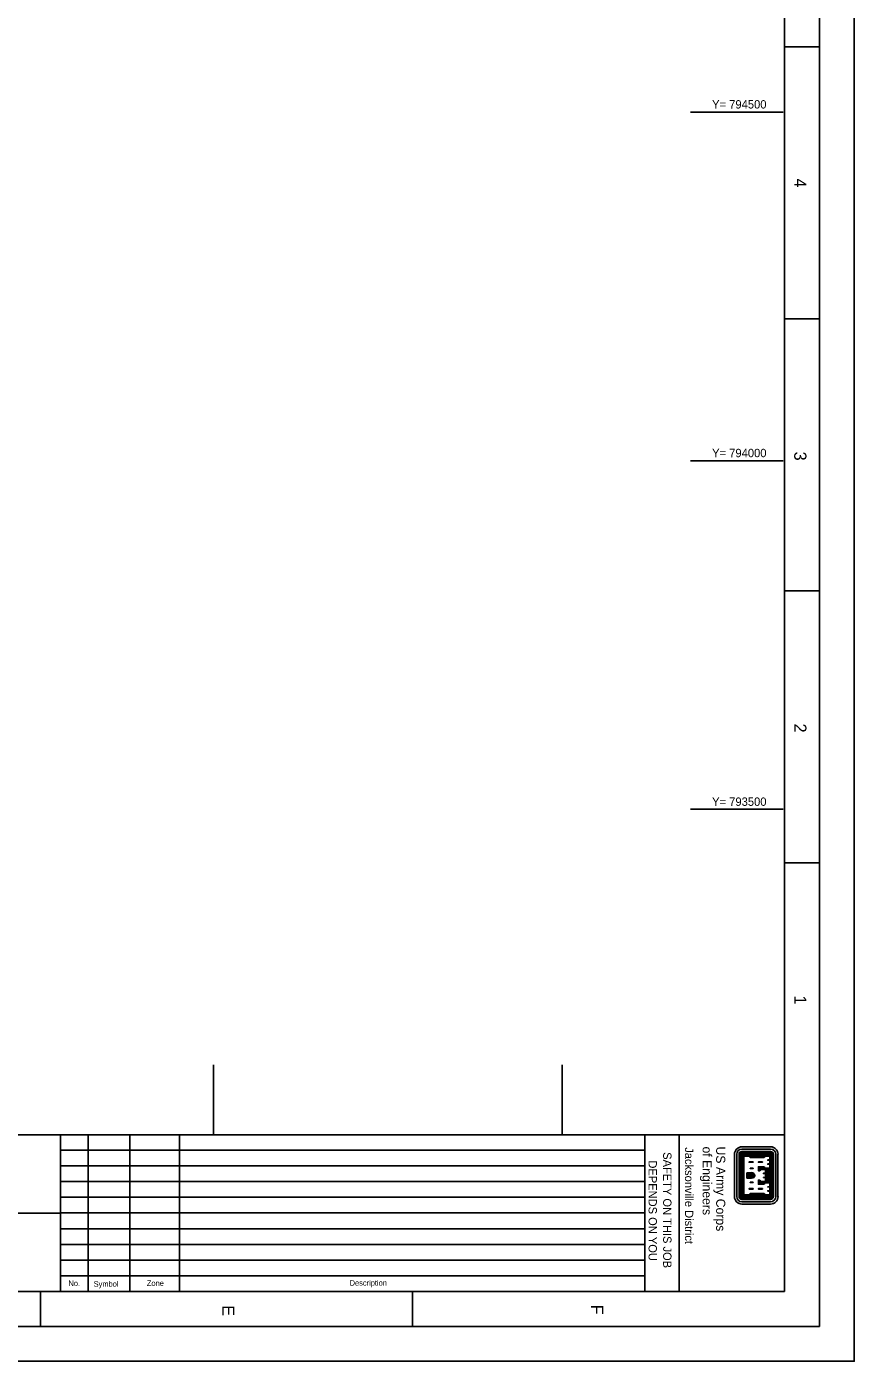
# Model space of a CAD drawing. Extents: x 604519 to 607919, y 792708 to 797108.
# Drawn here: x 606732 to 607919, y 792708 to 794622 of the extents above; entities that cross this region are included whole.
import ezdxf

# ---------------------------------------------------------------- set-up
doc = ezdxf.new("R2010")
doc.units = 0
for name, color, linetype in [('G-ANNO-NPLT', 7, 'Continuous'), ('G-ANNO-TEXT-LOGO', 7, 'Continuous'), ('G-ANNO-TEXT-TTLB', 7, 'Continuous'), ('G-ANNO-TTLB', 7, 'Continuous'), ('V-TOPO-COOR-STAT', 7, 'Continuous')]:
    doc.layers.add(name, color=color, linetype=linetype)

msp = doc.modelspace()

# ---------------------------------------------------------------- linework, layer by layer
at = {"layer": 'G-ANNO-NPLT'}
msp.add_lwpolyline([(607918.9, 797108.4), (607918.9, 792708.4), (604519, 792708.4), (604519, 797108.4)], close=True, dxfattribs=at)
msp.add_lwpolyline([(607868.9, 792708.4), (607918.9, 792708.4), (607918.9, 792758.4)], dxfattribs=at)
at = {"layer": 'G-ANNO-TEXT-LOGO'}
for p, q in [((607798.8, 793016), (607757.8, 793016)), ((607757.8, 793012.8), (607798.8, 793012.8)), ((607747, 793005.3), (607747, 792944.5)), ((607750.3, 792944.5), (607750.3, 793005.3)), ((607753.8, 792944.5), (607753.8, 793005.3)), ((607754.6, 792944.5), (607754.6, 793005.3)), ((607755.5, 792944.5), (607755.5, 793005.3)), ((607756.4, 792944.5), (607756.4, 793005.3)), ((607757.2, 792944.5), (607757.2, 793005.3)), ((607798.8, 793009.3), (607757.8, 793009.3)), ((607798.8, 793008.4), (607757.8, 793008.4)), ((607798.8, 793007.6), (607757.8, 793007.6)), ((607798.8, 793006.7), (607757.8, 793006.7)), ((607798.8, 793005.8), (607757.8, 793005.8)), ((607758.1, 792944.9), (607758.1, 793004.9)), ((607798.8, 793004.9), (607758.1, 793004.9)), ((607759, 792945.7), (607759, 793004.1)), ((607798.8, 793004.1), (607759, 793004.1)), ((607790.1, 793003.4), (607769.1, 793003.4)), ((607789.2, 793002.5), (607770.1, 793002.5)), ((607799.4, 792944.5), (607799.4, 793005.3)), ((607800.3, 792944.5), (607800.3, 793005.3)), ((607801.1, 792944.5), (607801.1, 793005.3)), ((607802, 792944.5), (607802, 793005.3)), ((607802.9, 792944.5), (607802.9, 793005.3)), ((607806.3, 793005.3), (607806.3, 792944.5)), ((607809.5, 792944.5), (607809.5, 793005.3)), ((607764.9, 792978.9), (607771.6, 792978.9)), ((607764.9, 792978.9), (607764.9, 792970.9)), ((607764.9, 792978.1), (607771.6, 792978.1)), ((607764.9, 792977.2), (607771.6, 792977.2)), ((607764.9, 792976.3), (607771.6, 792976.3)), ((607764.9, 792975.5), (607771.6, 792975.5)), ((607764.9, 792974.3), (607771.6, 792974.3)), ((607764.9, 792973.5), (607771.6, 792973.5)), ((607764.9, 792972.6), (607771.6, 792972.6)), ((607793.4, 792984.2), (607793.4, 792965.6)), ((607794.3, 792984.2), (607794.3, 792965.6)), ((607795.1, 792984.2), (607795.1, 792965.6)), ((607796, 792984.2), (607796, 792965.6)), ((607796.9, 792984.2), (607796.9, 792965.6)), ((607797.7, 792984.2), (607797.7, 792965.6)), ((607798.6, 792984.2), (607798.6, 792965.6)), ((607764.9, 792971.7), (607771.6, 792971.7)), ((607764.9, 792970.9), (607771.6, 792970.9)), ((607798.8, 792944), (607757.8, 792944)), ((607798.8, 792943.1), (607757.8, 792943.1)), ((607798.8, 792942.3), (607757.8, 792942.3)), ((607798.8, 792941.4), (607757.8, 792941.4)), ((607798.8, 792940.5), (607757.8, 792940.5)), ((607798.8, 792937.1), (607757.8, 792937.1)), ((607757.8, 792933.8), (607798.8, 792933.8)), ((607798.8, 792944.9), (607758.1, 792944.9)), ((607798.8, 792945.7), (607759, 792945.7)), ((607790, 792946.4), (607769.2, 792946.4)), ((607789.2, 792947.3), (607770.1, 792947.3))]:
    msp.add_line(p, q, dxfattribs=at)
for points in [[(607798.8, 793003.4), (607790.9, 793003.4), (607789.2, 793001.7), (607770.1, 793001.7), (607768.3, 793003.4), (607759.6, 793003.4), (607759.6, 792946.4), (607768.3, 792946.4), (607770.1, 792948.2), (607789.2, 792948.2), (607790.9, 792946.4), (607798.8, 792946.4), (607798.8, 792953.9), (607798.8, 792959.7), (607798.8, 792965.1), (607790.9, 792965.1), (607789.2, 792963.2), (607782.2, 792963.2), (607782.2, 792967.4), (607782.9, 792967.4), (607784.7, 792965.6), (607792.5, 792965.6), (607792.5, 792973.1), (607792.5, 792978.9), (607792.5, 792984.2), (607784.7, 792984.2), (607782.9, 792982.4), (607782.2, 792982.4), (607782.2, 792986.6), (607789.2, 792986.6), (607790.9, 792984.8), (607798.8, 792984.8), (607798.8, 792992.3), (607798.8, 792998.1), (607798.8, 793003.4)], [(607797.9, 793002.6), (607791.3, 793002.6), (607789.5, 793000.8), (607769.7, 793000.8), (607767.9, 793002.6), (607760.5, 793002.6), (607760.5, 792947.2), (607767.9, 792947.2), (607769.7, 792949.1), (607789.5, 792949.1), (607791.3, 792947.2), (607797.9, 792947.2), (607797.9, 792952.6), (607794.8, 792952.6), (607794.8, 792953.1), (607797.9, 792953.1), (607797.9, 792958.4), (607794.8, 792958.4), (607794.8, 792958.8), (607797.9, 792958.8), (607797.9, 792964.2), (607791.3, 792964.2), (607789.5, 792962.4), (607781.4, 792962.4), (607781.4, 792968.2), (607783.3, 792968.2), (607785.1, 792966.4), (607791.7, 792966.4), (607791.7, 792971.8), (607788.6, 792971.8), (607788.6, 792972.2), (607791.7, 792972.2), (607791.7, 792977.6), (607788.6, 792977.6), (607788.6, 792978.1), (607791.7, 792978.1), (607791.7, 792983.4), (607785.1, 792983.4), (607783.3, 792981.6), (607781.4, 792981.6), (607781.4, 792987.4), (607789.5, 792987.4), (607791.3, 792985.6), (607797.9, 792985.6), (607797.9, 792990.9), (607794.8, 792990.9), (607794.8, 792991.4), (607797.9, 792991.4), (607797.9, 792996.8), (607794.8, 792996.8), (607794.8, 792997.2), (607797.9, 792997.2), (607797.9, 793002.6)], [(607773.9, 792994.4), (607768, 792994.4), (607768, 792993.8), (607773.9, 792993.8), (607773.9, 792994.4)], [(607787.2, 792994.4), (607781.4, 792994.4), (607781.4, 792993.8), (607787.2, 792993.8), (607787.2, 792994.4)], [(607773.9, 792985.2), (607769.8, 792985.2), (607769.8, 792984.7), (607773.9, 792984.7), (607773.9, 792985.2)], [(607789.3, 792985.2), (607788.8, 792985.7), (607783.1, 792985.7), (607783.1, 792983.8), (607784.4, 792985.1), (607789.4, 792985.1)], [(607773.9, 792955.5), (607768, 792955.5), (607768, 792956), (607773.9, 792956), (607773.9, 792955.5)], [(607773.9, 792964.6), (607769.8, 792964.6), (607769.8, 792965.1), (607773.9, 792965.1), (607773.9, 792964.6)], [(607787.2, 792955.5), (607781.4, 792955.5), (607781.4, 792956), (607787.2, 792956), (607787.2, 792955.5)], [(607789.3, 792964.6), (607788.8, 792964.1), (607783.1, 792964.1), (607783.1, 792965.9), (607784.4, 792964.7), (607789.4, 792964.7)]]:
    msp.add_lwpolyline(points, dxfattribs=at)
for centre, major_axis, start_param, end_param in [((607757.8, 793005.3), (0, 10.7), 6.28317, 7.853966), ((607757.8, 793005.3), (0, 7.49), 6.28317, 7.853966), ((607798.9, 793005.3), (0, -10.7), 1.57078, 3.141576), ((607798.9, 793005.3), (0, -7.49), 1.57078, 3.141576), ((607757.8, 793005.3), (0, 4.02), 6.28317, 7.853966), ((607757.8, 793005.3), (0, 3.15), 6.28317, 7.853966), ((607757.8, 793005.3), (0, 2.28), 6.28317, 7.853966), ((607757.8, 793005.3), (0, 1.41), 6.28317, 7.853966), ((607757.8, 793005.3), (0, 0.546), 6.28317, 7.853966), ((607798.9, 793005.3), (0, -4.02), 1.57078, 3.141576), ((607798.9, 793005.3), (0, -3.15), 1.57078, 3.141576), ((607798.9, 793005.3), (0, -2.28), 1.57078, 3.141576), ((607798.9, 793005.3), (0, -1.41), 1.57078, 3.141576), ((607798.9, 793005.3), (0, -0.546), 1.57078, 3.141576), ((607771.2, 792976.5), (0, -2.08), 0.068794, 1.335689), ((607771.2, 792973.5), (0, 2.08), 4.947465, 6.214359), ((607771.2, 792973.5), (0, 2.95), 4.947465, 6.21436), ((607771.2, 792976.5), (0, -2.95), 0.068794, 1.335689), ((607771.2, 792973.5), (0, 4.69), 4.947465, 6.21436), ((607771.2, 792973.5), (0, 3.82), 4.947465, 6.21436), ((607771.2, 792976.5), (0, -3.82), 0.068795, 1.335689), ((607771.2, 792976.5), (0, -4.69), 0.068795, 1.335689), ((607771.2, 792973.5), (0, 5.55), 4.985832, 6.214359), ((607771.2, 792976.5), (0, -5.55), 0.068795, 1.29842), ((607757.8, 792944.6), (0, -10.7), 4.712373, 6.28317), ((607757.8, 792944.6), (0, 7.49), 1.570781, 3.141577), ((607757.8, 792944.6), (0, -4.02), 4.712373, 6.28317), ((607757.8, 792944.6), (0, -3.15), 4.712373, 6.28317), ((607757.8, 792944.6), (0, -2.28), 4.712373, 6.28317), ((607757.8, 792944.6), (0, -1.41), 4.712373, 6.28317), ((607757.8, 792944.6), (0, -0.546), 4.712373, 6.28317), ((607798.9, 792944.6), (0, -4.02), 6.283169, 7.853965), ((607798.9, 792944.6), (0, -3.15), 6.283169, 7.853965), ((607798.9, 792944.6), (0, -2.28), 6.283169, 7.853965), ((607798.9, 792944.6), (0, -1.41), 6.283169, 7.853965), ((607798.9, 792944.6), (0, -0.546), 6.283169, 7.853965), ((607798.9, 792944.6), (0, -10.7), 6.283169, 7.853965), ((607798.9, 792944.6), (0, -7.49), 6.28317, 7.853966)]:
    msp.add_ellipse(centre, major_axis=major_axis, ratio=0.99964, start_param=start_param, end_param=end_param, dxfattribs=at)
at = {"layer": 'G-ANNO-TTLB'}
for p, q in [((607868.9, 794593.4), (607818.9, 794593.4)), ((607868.9, 794203.4), (607818.9, 794203.4)), ((607868.9, 793813.4), (607818.9, 793813.4)), ((607868.9, 793423.4), (607818.9, 793423.4)), ((607818.9, 793033.4), (604619, 793033.4)), ((606780.7, 793033.4), (606780.7, 792808.4)), ((606820.5, 793033.4), (606820.5, 792808.4)), ((606880.5, 793033.4), (606880.5, 792808.4)), ((606951.7, 793033.4), (606951.7, 792808.4)), ((607618.6, 793034), (607618.6, 792809)), ((607667.7, 793033.4), (607667.7, 792808.4)), ((607618.6, 793011.1), (606780.7, 793011.1)), ((607618.6, 792988.6), (606780.7, 792988.6)), ((607618.6, 792966.1), (606780.7, 792966.1)), ((607618.6, 792943.6), (606780.7, 792943.6)), ((605921.1, 792921.6), (606780.7, 792920.9)), ((606780.7, 792920.9), (606745.3, 792920.9)), ((607618.6, 792921.1), (606780.7, 792921.1)), ((607618.6, 792898.6), (606780.7, 792898.6)), ((607618.6, 792876.1), (606780.7, 792876.1)), ((607618.6, 792853.6), (606780.7, 792853.6)), ((607618.6, 792831.1), (606780.7, 792831.1)), ((606752.1, 792758.4), (606752.1, 792808.4)), ((607285.4, 792758.4), (607285.4, 792808.4))]:
    msp.add_line(p, q, dxfattribs=at)
for points in [[(604569, 797058.4), (604569, 792758.4), (607868.9, 792758.4), (607868.9, 797058.4)], [(607818.9, 792808.4), (607818.9, 796933.4), (604619, 796933.4), (604619, 792808.4)]]:
    msp.add_lwpolyline(points, close=True, dxfattribs=at)
at = {"layer": 'V-TOPO-COOR-STAT'}
for p, q in [((607683.9, 794500), (607816.8, 794500)), ((607683.9, 794000), (607816.8, 794000)), ((607683.9, 793500), (607816.8, 793500)), ((607000, 793033.4), (607000, 793133.4)), ((607500, 793033.4), (607500, 793133.4))]:
    msp.add_line(p, q, dxfattribs=at)

# ---------------------------------------------------------------- texts
at = {"layer": 'G-ANNO-TEXT-TTLB'}
for s, height, rotation, p in [('Jacksonville District', 11.9, 270, (607676.2, 793015.4)), ('of Engineers', 13.086, 270, (607701.5, 793016.4)), ('US Army Corps', 13.086, 270, (607720.9, 793016.4)), ('DEPENDS ON YOU', 11.9, 270, (607624, 792996.5)), ('SAFETY ON THIS JOB', 11.9, 270, (607644.9, 793008.3)), ('No.', 8, 360, (606792.3, 792816.3)), ('Symbol', 8, 360, (606828.4, 792815.3)), ('Zone', 8, 360, (606904.7, 792816.5)), ('Description', 8, 360, (607195.4, 792816.8))]:
    msp.add_text(s, height=height, rotation=rotation, dxfattribs=at).set_placement(p)
at = {"layer": 'G-ANNO-TTLB'}
for s, p in [('4', (607832.8, 794404.7)), ('3', (607832.8, 794013)), ('2', (607832.8, 793623)), ('1', (607832.8, 793233)), ('E', (607012.8, 792788.8)), ('F', (607541.6, 792789.6))]:
    msp.add_text(s, height=17.5, rotation=270, dxfattribs=at).set_placement(p)
at = {"layer": 'V-TOPO-COOR-STAT'}
for s, p in [('Y= 794500', (607715, 794505)), ('Y= 794000', (607715, 794005)), ('Y= 793500', (607715, 793505))]:
    msp.add_text(s, height=12, dxfattribs=at).set_placement(p)

doc.saveas('drawing.dxf')
